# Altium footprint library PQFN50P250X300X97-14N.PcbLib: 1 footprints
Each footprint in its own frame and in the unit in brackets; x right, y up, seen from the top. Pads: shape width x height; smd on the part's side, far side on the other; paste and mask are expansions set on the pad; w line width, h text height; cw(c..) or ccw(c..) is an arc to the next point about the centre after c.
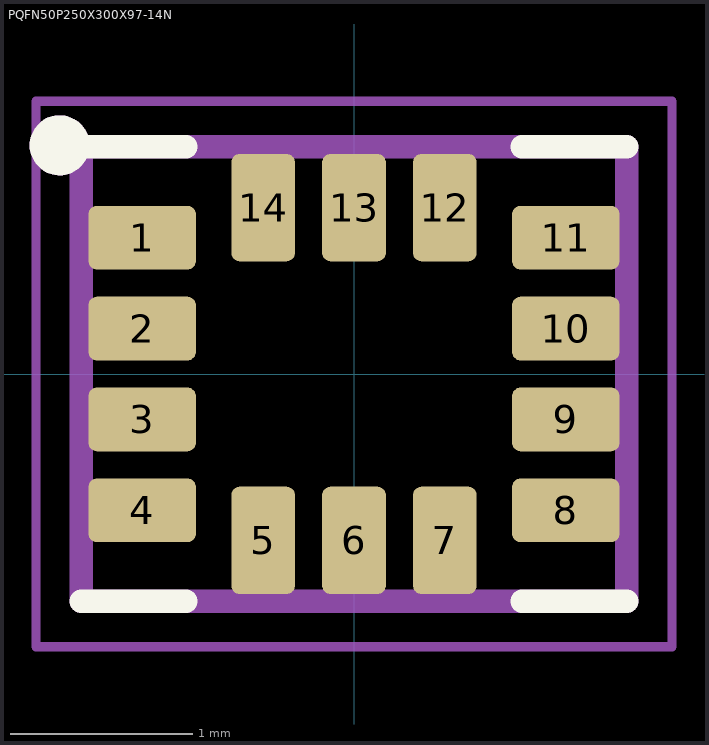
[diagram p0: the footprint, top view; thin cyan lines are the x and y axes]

## PQFN50P250X300X97-14N [mm]
pads (14):
  rrect25% 0.59x0.35 smd: 1(-1.165,0.75) 2(-1.165,0.25) 3(-1.165,-0.25) 4(-1.165,-0.75) 8(1.165,-0.75) 9(1.165,-0.25) 10(1.165,0.25) 11(1.165,0.75)
  rrect25% 0.35x0.59 smd: 5(-0.5,-0.915) 6(0,-0.915) 7(0.5,-0.915) 12(0.5,0.915) 13(0,0.915) 14(-0.5,0.915)
Top Overlay:
  circle w0.178: c-1.619,1.258 r0.076
  lines w0.127: -1.5,-1.25 -0.925,-1.25 ; -1.5,1.25 -0.925,1.25 ; 0.925,-1.25 1.5,-1.25 ; 0.925,1.25 1.5,1.25
Assembly Top:
  circle w0.178: c-1.619,1.258 r0.076
  lines w0.127: -1.5,-1.25 1.5,-1.25 1.5,1.25 -1.5,1.25 -1.5,-1.25
Courtyard Top:
  lines w0.05: -1.75,-1.5 1.75,-1.5 1.75,1.5 -1.75,1.5 -1.75,-1.5
3D body "step_temp.STEP": height 0.97, standoff 0, extent -1.5,-1.25 1.5,1.25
